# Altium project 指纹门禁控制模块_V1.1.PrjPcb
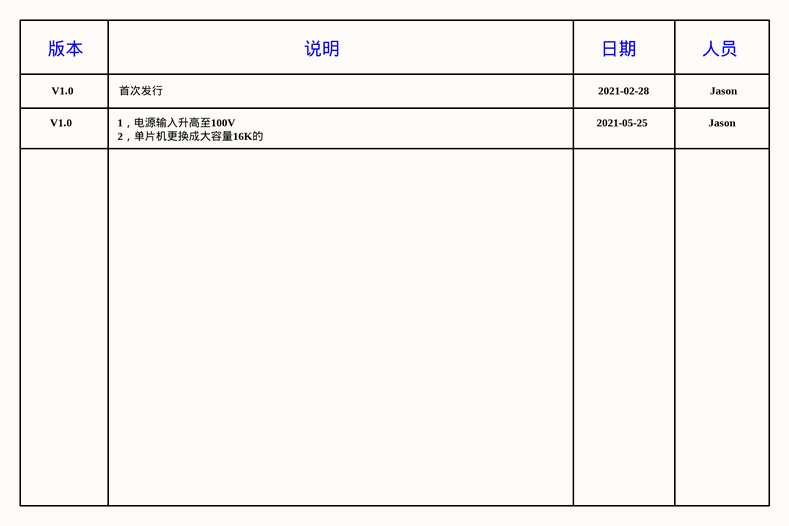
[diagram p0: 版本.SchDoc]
2 sheets, 41 parts. Net scope: global (net labels, ports and power ports of the same name join across sheets).
Board file: 指纹门禁控制模块_V1.1.PcbDoc
Sheets:
  版本.SchDoc
  指纹门禁控制模块_V1.1.SchDoc

## Sheet 版本.SchDoc
size A4

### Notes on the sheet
- 版本
- V1.0
- 首次发行
- 说明
- 2021-02-28
- 日期
- 人员
- Jason
- 1，电源输入升高至100V
- 2，单片机更换成大容量16K的
- 2021-05-25

## Sheet 指纹门禁控制模块_V1.1.SchDoc
size A3
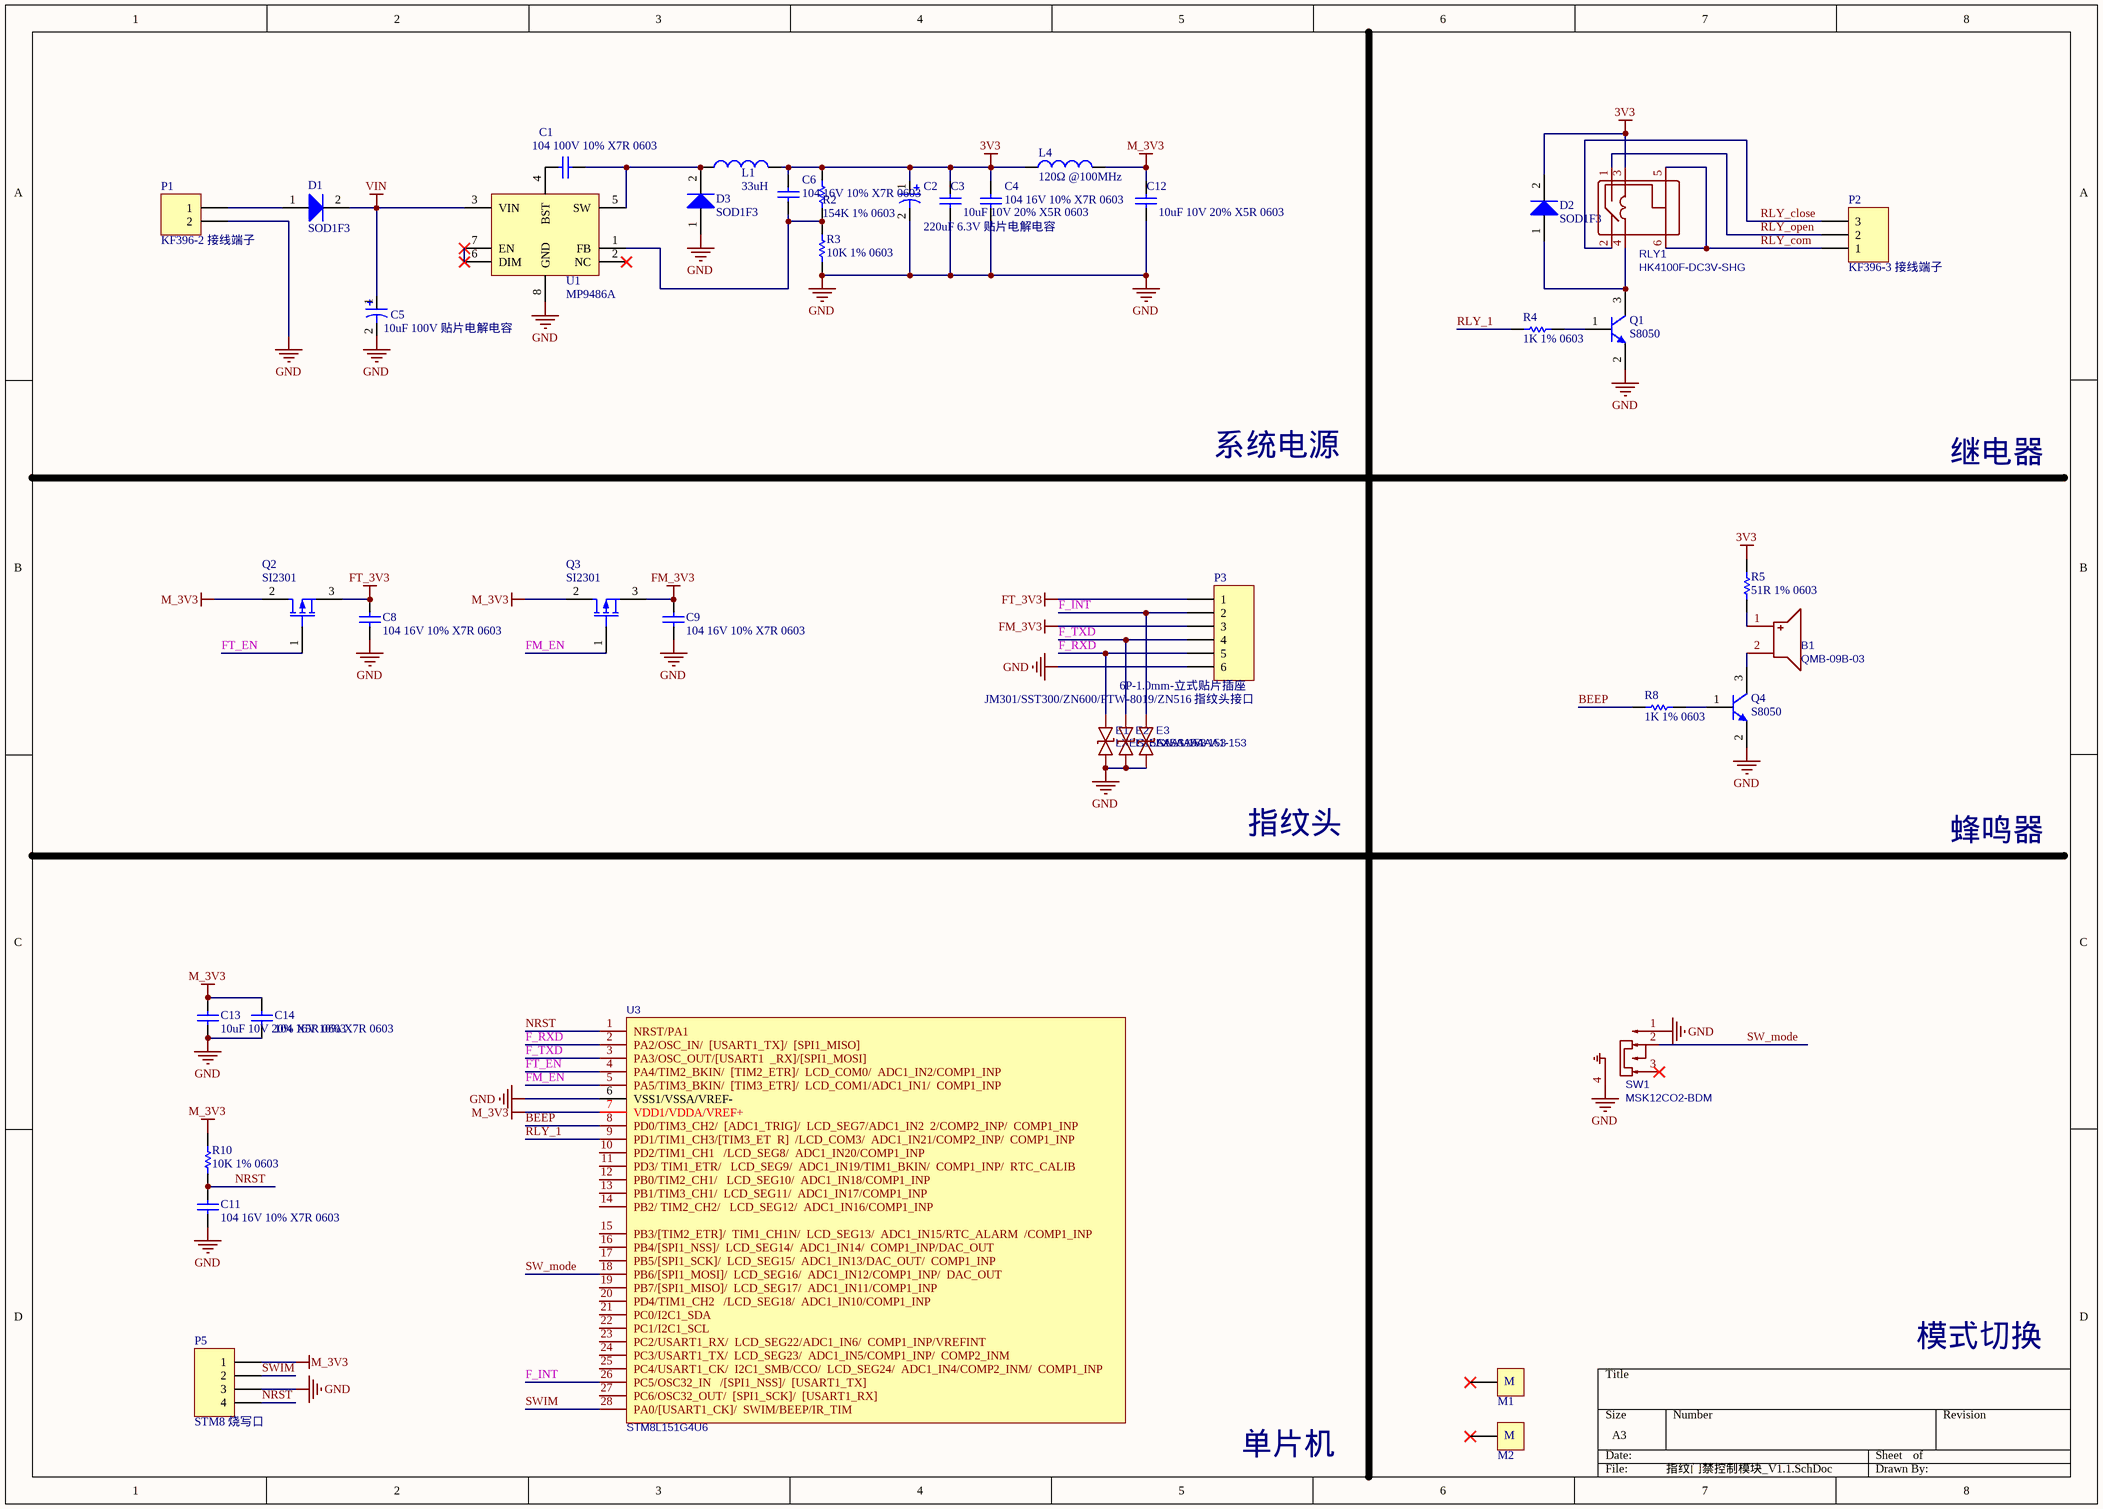
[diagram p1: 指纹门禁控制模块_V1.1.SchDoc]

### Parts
B1  QMB-09B-03  [BUZZER-9MM]
C1  104 100V 10% X7R 0603  [C0603]
C2  220uF 6.3V 贴片电解电容  [CAP-D6.3XH7.7]
C3  10uF 10V 20% X5R 0603  [C0603]
C4  104 16V 10% X7R 0603  [C0603]
C5  10uF 100V 贴片电解电容  [CAP-D6.3XH7.7]
C6  104 16V 10% X7R 0603  [C0603]
C8  104 16V 10% X7R 0603  [C0603]
C9  104 16V 10% X7R 0603  [C0603]
C11  104 16V 10% X7R 0603  [C0603]
C12  10uF 10V 20% X5R 0603  [C0603]
C13  10uF 10V 20% X5R 0603  [C0603]
C14  104 16V 10% X7R 0603  [C0603]
D1  SOD1F3  [SOD-123]
D2  SOD1F3  [SOD-123]
D3  SOD1F3  [SOD-123]
E1  LXES15AAA1-153  [R0402]
E2  LXES15AAA1-153  [R0402]
E3  LXES15AAA1-153  [R0402]
L1  33uH  [L-SMD-5.8X5.2]
L4  120Ω @100MHz  [R0603]
M1  MARK  [MARK]  (value not drawn)
M2  MARK  [MARK]  (value not drawn)
P1  KF396-2 接线端子  [KF396-2]
P2  KF396-3 接线端子  [KF396-3]
P3  6P-1.0mm-立式贴片插座  [SH 1.0_LS_6P]
P5  STM8 烧写口  [HDR1X4]
Q1  S8050  [SOT-23]
Q2  SI2301  [SOT-23]
Q3  SI2301  [SOT-23]
Q4  S8050  [SOT-23]
R2  154K 1% 0603  [R0603]
R3  10K 1% 0603  [R0603]
R4  1K 1% 0603  [R0603]
R5  51R 1% 0603  [R0603]
R8  1K 1% 0603  [R0603]
R10  10K 1% 0603  [R0603]
RLY1  HK4100F-DC3V-SHG  [RELAY-TH_HK4100F-XXX-XXXX]
SW1  MSK12CO2-BDM  [SW-SMD_MSK12CO2-BDM]
U1  MP9486A  [SOP-8E]
U3  STM8L151G4U6  [UFQFPN-28]

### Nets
3V3: C2.1 C3.1 C4.1 C6.1 D2.2(K) L1.2 L4.2 R2.1 R5.1 RLY1.3
FM_3V3: C9.1 P3.3 Q3.3(S)
FT_3V3: C8.1 P3.1 Q2.3(S)
GND: C2.2 C3.2 C4.2 C5.2 C8.2 C9.2 C11.1 C12.2 C13.2 C14.1 D3.1(A) E1.1 E2.1 E3.1 P1.2 P3.6 P5.3 Q1.2(B) Q4.2(B) R3.2 SW1.1 SW1.4 U1.8(GND) U3.6(VSS1/VSSA/VREF-)
M_3V3: C12.1 C13.1 C14.2 L4.1 P5.1 Q2.2(G) Q3.2(G) R10.1 U3.7(VDD1/VDDA/VREF+)
VIN: C5.1 D1.2(K) U1.3(VIN)
BEEP: R8.1 U3.8(PD0/TIM3_CH2/__[ADC1_TRIG]/__LCD_SEG7/ADC1_IN2__2/COMP2_INP/__COMP1_INP)
F_INT: E3.2 P3.2 U3.26(PC5/OSC32_IN___/[SPI1_NSS]/__[USART1_TX])
F_RXD: E1.2 P3.5 U3.2(PA2/OSC_IN/__[USART1_TX]/__[SPI1_MISO])
F_TXD: E2.2 P3.4 U3.3(PA3/OSC_OUT/[USART1___RX]/[SPI1_MOSI])
FM_EN: Q3.1(D) U3.5(PA5/TIM3_BKIN/__[TIM3_ETR]/__LCD_COM1/ADC1_IN1/__COMP1_INP)
FT_EN: Q2.1(D) U3.4(PA4/TIM2_BKIN/__[TIM2_ETR]/__LCD_COM0/__ADC1_IN2/COMP1_INP)
NRST: C11.2 P5.4 R10.2 U3.1(NRST/PA1)
RLY_1: R4.1 U3.9(PD1/TIM1_CH3/[TIM3_ET__R]__/LCD_COM3/__ADC1_IN21/COMP2_INP/__COMP1_INP)
RLY_close: P2.3 RLY1.2
RLY_com: P2.1 RLY1.5 RLY1.6
RLY_open: P2.2 RLY1.1
SW_mode: SW1.2 U3.18(PB6/[SPI1_MOSI]/__LCD_SEG16/__ADC1_IN12/COMP1_INP/__DAC_OUT)
SWIM: P5.2 U3.28(PA0/[USART1_CK]/__SWIM/BEEP/IR_TIM)
NetB1_1: B1.1 R5.2
NetB1_2: B1.2 Q4.3(E)
NetC1_1: C1.1 U1.4(BST)
NetC1_2: C1.2 D3.2(K) L1.1 U1.5(SW)
NetC6_2: C6.2 R2.2 R3.1 U1.1(FB)
NetD1_1: D1.1(A) P1.1
NetD2_1: D2.1(A) Q1.3(E) RLY1.4
NetQ1_1: Q1.1(C) R4.2
NetQ4_1: Q4.1(C) R8.2
NetU1_6: U1.6(DIM) U1.7(EN)

Not connected (* = marked no-connect by the designer): M1 1*; M2 1*; SW1 3*; U1 2(NC)*; U3 10(PD2/TIM1_CH1___/LCD_SEG8/__ADC1_IN20/COMP1_INP) 11(PD3/_TIM1_ETR/___LCD_SEG9/__ADC1_IN19/TIM1_BKIN/__COMP1_INP/__RTC_CALIB) 12(PB0/TIM2_CH1/___LCD_SEG10/__ADC1_IN18/COMP1_INP) 13(PB1/TIM3_CH1/__LCD_SEG11/__ADC1_IN17/COMP1_INP) 14(PB2/_TIM2_CH2/___LCD_SEG12/__ADC1_IN16/COMP1_INP) 15(PB3/[TIM2_ETR]/__TIM1_CH1N/__LCD_SEG13/__ADC1_IN15/RTC_ALARM__/COMP1_INP) 16(PB4/[SPI1_NSS]/__LCD_SEG14/__ADC1_IN14/__COMP1_INP/DAC_OUT) 17(PB5/[SPI1_SCK]/__LCD_SEG15/__ADC1_IN13/DAC_OUT/__COMP1_INP) 19(PB7/[SPI1_MISO]/__LCD_SEG17/__ADC1_IN11/COMP1_INP) 20(PD4/TIM1_CH2___/LCD_SEG18/__ADC1_IN10/COMP1_INP) 21(PC0/I2C1_SDA) 22(PC1/I2C1_SCL) 23(PC2/USART1_RX/__LCD_SEG22/ADC1_IN6/__COMP1_INP/VREFINT) 24(PC3/USART1_TX/__LCD_SEG23/__ADC1_IN5/COMP1_INP/__COMP2_INM) 25(PC4/USART1_CK/__I2C1_SMB/CCO/__LCD_SEG24/__ADC1_IN4/COMP2_INM/__COMP1_INP) 27(PC6/OSC32_OUT/__[SPI1_SCK]/__[USART1_RX])

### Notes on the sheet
- 系统电源
- 继电器
- 指纹头
- 蜂鸣器
- 模式切换
- 单片机

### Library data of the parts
B1 = QMB-09B-03: BOM_Manufacturer: HNDZ; Contributor: LCSC; BOM_Paste Type: expand; BOM_Assembly Type: manualWeld
C1 C3 C4 C6 C8 C9 C11-C14 = CapN: CAP; 制造商: SAMSUNG
C2 C5 = CapH: 100uF,35V,插件电解电容; Designer: Anson Chen
D1-D3 = 1N4007
E1-E3 = LXES15AAA1-153: BOM_Manufacturer: MuRata
L1 = InductorDM: GCD54-330MC; Code_IEC: 1005; Value: 10mH
L4 = Inductor: CBW160808U121T
P1 = Header 2: Header, 2-Pin
P2 = Header 3: Header, 3-Pin
P3 = Header 6: Header, 6-Pin
P5 = Header 4: Header, 4-Pin
Q1 Q4 = NPN: NPN晶体管
Q2 Q3 = MOSFET-P
R2-R5 R8 R10 = Res1: Resistor
RLY1 = HK4100F-DC3V-SHG: BOM_Manufacturer: Ningbo Keke New Era Appliance; Contributor: LCSC; BOM_Paste Type: expand; BOM_Assembly Type: manualWeld
SW1 = MSK12CO2-BDM: BOM_Manufacturer: SHOU HAN; Contributor: LCSC
U1 = MP9486A: 100V 输入，3.5A 峰值电流限 降压转换器
U3 = STM8L151G4U6: BOM_Manufacturer: STMicroelectronics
